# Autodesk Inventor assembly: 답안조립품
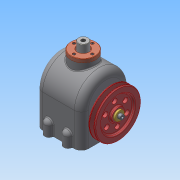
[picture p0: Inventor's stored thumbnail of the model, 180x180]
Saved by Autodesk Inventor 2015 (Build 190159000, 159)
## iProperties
Created: 2023-03
Part Number: 답안조립품
Document SubType Name: Assembly
Designer: home
Author: home
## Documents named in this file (22)
- C:\Users\home\Desktop\730306V1015\답안조립품.iam
- C:\Users\home\Desktop\730306V1015\E형 멈춤링 13 x 12.ipt
- C:\Users\home\Desktop\730306V1015\V-벨트풀리.ipt
- C:\Users\home\Desktop\730306V1015\고정핀.ipt
- C:\Users\home\Desktop\730306V1015\뒷커버.ipt
- C:\Users\home\Desktop\730306V1015\링크.ipt
- C:\Users\home\Desktop\730306V1015\멈춤링 25 x 1.2.ipt
- 멈춤링 25 x 1.2.ipt
- C:\Users\home\Desktop\730306V1015\베어링 6205.ipt
- 베어링 6205.ipt
- C:\Users\home\Desktop\730306V1015\본체.ipt
- C:\Users\home\Desktop\730306V1015\볼트 M4 x 12.ipt
- C:\Users\home\Desktop\730306V1015\볼트 M8 x 16.ipt
- C:\Users\home\Desktop\730306V1015\부시.ipt
- C:\Users\home\Desktop\730306V1015\슬라이더.ipt
- C:\Users\home\Desktop\730306V1015\앞커버.ipt
- C:\Users\home\Desktop\730306V1015\엔드캡.ipt
- C:\Users\home\Desktop\730306V1015\오일실 25 40 8.ipt
- 오일실 25 40 8.ipt
- C:\Users\home\Desktop\730306V1015\윗커버.ipt
- C:\Users\home\Desktop\730306V1015\키 6x6x14.ipt
- C:\Users\home\Desktop\730306V1015\편심축.ipt
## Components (3 placed, 3 different names)
1. E형 멈춤링 13 x 12:1
2. V-벨트풀리:1
3. 고정핀:1
